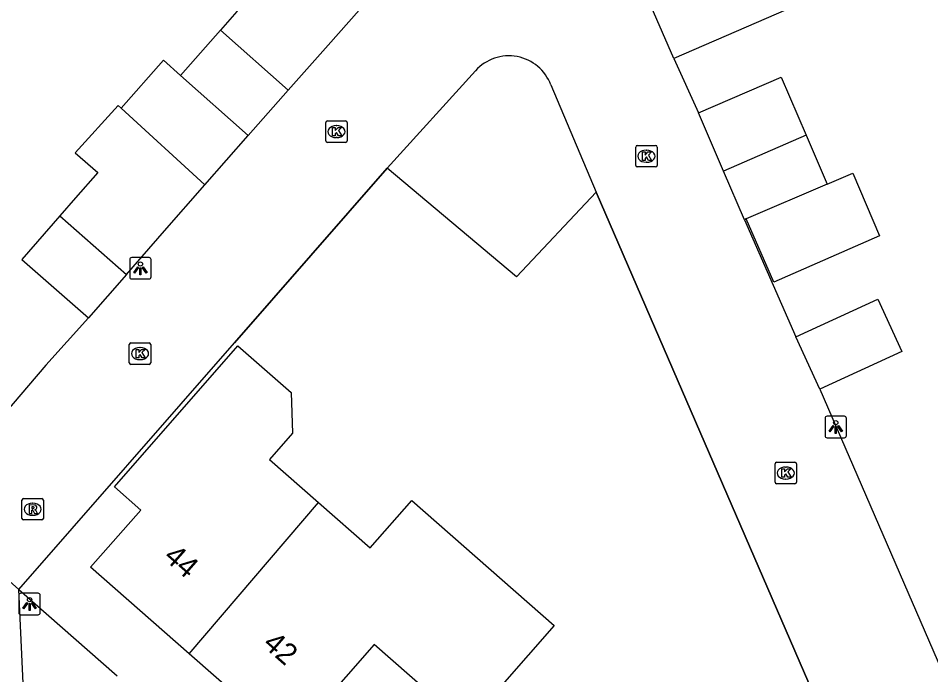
# Model space of a CAD drawing. Extents: x 158474 to 159560, y 388525 to 389605.
# Drawn here: x 158891.36 to 158933.91, y 388910.55 to 388941.14 of the extents above; entities that cross this region are included whole.
import ezdxf

# ---------------------------------------------------------------- set-up
doc = ezdxf.new("R2010")
doc.units = 0
for name, color, linetype in [('IMGEO_Kolk', 7, 'Continuous'), ('IMGEO_Lichtpunt', 7, 'Continuous'), ('IMGEO_Muur', 7, 'Continuous'), ('IMGEO_Pand', 7, 'Continuous'), ('IMGEO_Pand_nummerreeks', 7, 'Continuous'), ('IMGEO_Rijbaan_lokaal_open', 7, 'Continuous'), ('IMGEO_Rioolput', 7, 'Continuous'), ('IMGEO_Voetpad_open', 7, 'Continuous')]:
    doc.layers.add(name, color=color, linetype=linetype)

msp = doc.modelspace()

# ---------------------------------------------------------------- linework, layer by layer
at = {"layer": 'IMGEO_Kolk'}
for p, q in [((158905.696, 388935.435), (158905.696, 388936.287)), ((158905.771, 388936.361), (158906.623, 388936.361)), ((158906.184, 388936.141), (158906.209, 388936.141)), ((158906.697, 388936.287), (158906.697, 388935.435)), ((158906.207, 388935.581), (158906.182, 388935.581)), ((158906.623, 388935.361), (158905.771, 388935.361)), ((158920.223, 388935.216), (158921.075, 388935.216)), ((158920.148, 388934.29), (158920.148, 388935.142)), ((158920.636, 388934.996), (158920.661, 388934.996)), ((158921.149, 388935.142), (158921.149, 388934.29)), ((158920.659, 388934.436), (158920.634, 388934.436)), ((158921.075, 388934.216), (158920.223, 388934.216)), ((158896.535, 388925.089), (158896.535, 388925.941)), ((158896.61, 388926.015), (158897.462, 388926.015)), ((158897.023, 388925.795), (158897.048, 388925.795)), ((158897.536, 388925.941), (158897.536, 388925.089)), ((158897.462, 388925.015), (158896.61, 388925.015)), ((158897.046, 388925.235), (158897.021, 388925.235)), ((158926.646, 388919.524), (158926.646, 388920.376)), ((158926.721, 388920.45), (158927.573, 388920.45)), ((158927.647, 388920.376), (158927.647, 388919.524)), ((158927.134, 388920.23), (158927.159, 388920.23)), ((158927.573, 388919.45), (158926.721, 388919.45)), ((158927.157, 388919.67), (158927.132, 388919.67))]:
    msp.add_line(p, q, dxfattribs=at)
for points in [[(158905.696, 388935.435), (158905.696, 388936.287)], [(158905.771, 388936.361), (158906.623, 388936.361)], [(158906.017, 388936.061), (158906.14, 388936.061), (158906.14, 388935.91), (158906.27, 388936.061), (158906.434, 388936.061), (158906.288, 388935.91), (158906.441, 388935.661), (158906.289, 388935.661), (158906.204, 388935.825), (158906.14, 388935.758), (158906.14, 388935.661), (158906.017, 388935.661), (158906.017, 388936.061)], [(158906.697, 388936.287), (158906.697, 388935.435)], [(158906.623, 388935.361), (158905.771, 388935.361)], [(158920.223, 388935.216), (158921.075, 388935.216)], [(158920.148, 388934.29), (158920.148, 388935.142)], [(158920.469, 388934.916), (158920.592, 388934.916), (158920.592, 388934.765), (158920.722, 388934.916), (158920.886, 388934.916), (158920.74, 388934.765), (158920.893, 388934.516), (158920.741, 388934.516), (158920.656, 388934.68), (158920.592, 388934.613), (158920.592, 388934.516), (158920.469, 388934.516), (158920.469, 388934.916)], [(158921.149, 388935.142), (158921.149, 388934.29)], [(158921.075, 388934.216), (158920.223, 388934.216)], [(158896.535, 388925.089), (158896.535, 388925.941)], [(158896.61, 388926.015), (158897.462, 388926.015)], [(158897.536, 388925.941), (158897.536, 388925.089)], [(158896.856, 388925.715), (158896.979, 388925.715), (158896.979, 388925.564), (158897.109, 388925.715), (158897.273, 388925.715), (158897.127, 388925.564), (158897.28, 388925.315), (158897.128, 388925.315), (158897.043, 388925.479), (158896.979, 388925.412), (158896.979, 388925.315), (158896.856, 388925.315), (158896.856, 388925.715)], [(158897.462, 388925.015), (158896.61, 388925.015)], [(158926.646, 388919.524), (158926.646, 388920.376)], [(158926.721, 388920.45), (158927.573, 388920.45)], [(158927.647, 388920.376), (158927.647, 388919.524)], [(158926.967, 388920.15), (158927.09, 388920.15), (158927.09, 388919.999), (158927.22, 388920.15), (158927.384, 388920.15), (158927.238, 388919.999), (158927.391, 388919.75), (158927.239, 388919.75), (158927.154, 388919.914), (158927.09, 388919.847), (158927.09, 388919.75), (158926.967, 388919.75), (158926.967, 388920.15)], [(158927.573, 388919.45), (158926.721, 388919.45)]]:
    msp.add_lwpolyline(points, dxfattribs=at)
for centre, start, end in [((158905.773, 388936.285), 91.552, 178.448), ((158905.773, 388936.285), 91.552, 178.448), ((158906.621, 388936.285), 1.552, 88.448), ((158906.621, 388936.285), 1.552, 88.448), ((158905.773, 388935.437), 181.552, 268.448), ((158905.773, 388935.437), 181.552, 268.448), ((158906.621, 388935.437), 271.552, 358.448), ((158906.621, 388935.437), 271.552, 358.448), ((158920.225, 388935.14), 91.552, 178.448), ((158920.225, 388935.14), 91.552, 178.448), ((158921.073, 388935.14), 1.552, 88.448), ((158921.073, 388935.14), 1.552, 88.448), ((158920.225, 388934.292), 181.552, 268.448), ((158920.225, 388934.292), 181.552, 268.448), ((158921.073, 388934.292), 271.552, 358.448), ((158921.073, 388934.292), 271.552, 358.448), ((158896.612, 388925.939), 91.552, 178.448), ((158896.612, 388925.939), 91.552, 178.448), ((158897.46, 388925.939), 1.552, 88.448), ((158897.46, 388925.939), 1.552, 88.448), ((158896.612, 388925.091), 181.552, 268.448), ((158896.612, 388925.091), 181.552, 268.448), ((158897.46, 388925.091), 271.552, 358.448), ((158897.46, 388925.091), 271.552, 358.448), ((158926.723, 388920.374), 91.552, 178.448), ((158926.723, 388920.374), 91.552, 178.448), ((158927.571, 388920.374), 1.552, 88.448), ((158927.571, 388920.374), 1.552, 88.448), ((158926.723, 388919.526), 181.552, 268.448), ((158926.723, 388919.526), 181.552, 268.448), ((158927.571, 388919.526), 271.552, 358.448), ((158927.571, 388919.526), 271.552, 358.448)]:
    msp.add_arc(centre, 0.0765, start, end, dxfattribs=at)
for centre, major_axis, ratio, start_param, end_param in [((158906.183, 388935.861), (-0.387, 0.002), 0.722429, 4.712389, 7.853982), ((158906.208, 388935.861), (-0.39, 0.002), 0.717154, 1.570796, 4.712389), ((158920.635, 388934.716), (-0.387, 0.002), 0.722429, 4.712389, 7.853982), ((158920.66, 388934.716), (-0.39, 0.002), 0.717154, 1.570796, 4.712389), ((158897.022, 388925.515), (-0.387, 0.002), 0.722429, 4.712389, 7.853982), ((158897.047, 388925.515), (-0.39, 0.002), 0.717154, 1.570796, 4.712389), ((158927.133, 388919.95), (-0.387, 0.002), 0.722429, 4.712389, 7.853982), ((158927.158, 388919.95), (-0.39, 0.002), 0.717154, 1.570796, 4.712389)]:
    msp.add_ellipse(centre, major_axis=major_axis, ratio=ratio, start_param=start_param, end_param=end_param, dxfattribs=at)
at = {"layer": 'IMGEO_Lichtpunt'}
for p, q in [((158896.556, 388929.895), (158896.556, 388929.088)), ((158896.556, 388929.895), (158896.556, 388929.088)), ((158897.458, 388929.99), (158896.65, 388929.99)), ((158897.458, 388929.99), (158896.65, 388929.99)), ((158897.552, 388929.088), (158897.552, 388929.895)), ((158897.552, 388929.088), (158897.552, 388929.895)), ((158896.65, 388928.994), (158897.458, 388928.994)), ((158896.65, 388928.994), (158897.458, 388928.994)), ((158928.978, 388922.499), (158928.978, 388921.692)), ((158928.978, 388922.499), (158928.978, 388921.692)), ((158929.88, 388922.594), (158929.072, 388922.594)), ((158929.88, 388922.594), (158929.072, 388922.594)), ((158929.974, 388921.692), (158929.974, 388922.499)), ((158929.974, 388921.692), (158929.974, 388922.499)), ((158929.072, 388921.598), (158929.88, 388921.598)), ((158929.072, 388921.598), (158929.88, 388921.598)), ((158892.287, 388914.345), (158891.479, 388914.345)), ((158892.287, 388914.345), (158891.479, 388914.345)), ((158891.385, 388914.25), (158891.385, 388913.443)), ((158891.385, 388914.25), (158891.385, 388913.443)), ((158892.381, 388913.443), (158892.381, 388914.25)), ((158892.381, 388913.443), (158892.381, 388914.25)), ((158891.479, 388913.349), (158892.287, 388913.349)), ((158891.479, 388913.349), (158892.287, 388913.349))]:
    msp.add_line(p, q, dxfattribs=at)
for points in [[(158896.93, 388929.559), (158896.969, 388929.531), (158896.781, 388929.269), (158896.743, 388929.296), (158896.93, 388929.559)], [(158897.032, 388929.511), (158897.079, 388929.511), (158897.079, 388929.189), (158897.032, 388929.189), (158897.032, 388929.511)], [(158897.142, 388929.531), (158897.18, 388929.558), (158897.367, 388929.296), (158897.328, 388929.268), (158897.142, 388929.531)], [(158929.352, 388922.163), (158929.391, 388922.135), (158929.203, 388921.873), (158929.165, 388921.9), (158929.352, 388922.163)], [(158929.454, 388922.115), (158929.501, 388922.115), (158929.501, 388921.793), (158929.454, 388921.793), (158929.454, 388922.115)], [(158929.564, 388922.135), (158929.602, 388922.162), (158929.789, 388921.9), (158929.75, 388921.872), (158929.564, 388922.135)], [(158891.759, 388913.914), (158891.798, 388913.886), (158891.61, 388913.624), (158891.572, 388913.651), (158891.759, 388913.914)], [(158891.971, 388913.886), (158892.009, 388913.913), (158892.196, 388913.651), (158892.157, 388913.623), (158891.971, 388913.886)], [(158891.861, 388913.866), (158891.908, 388913.866), (158891.908, 388913.544), (158891.861, 388913.544), (158891.861, 388913.866)]]:
    msp.add_lwpolyline(points, dxfattribs=at)
for centre in [(158897.055, 388929.693), (158929.477, 388922.297), (158891.884, 388914.048)]:
    msp.add_circle(centre, 0.0994, dxfattribs=at)
for centre, start, end in [((158896.65, 388929.895), 90, 180), ((158896.65, 388929.895), 90, 180), ((158897.458, 388929.895), 0, 90), ((158897.458, 388929.895), 0, 90), ((158896.65, 388929.088), 180, 270), ((158896.65, 388929.088), 180, 270), ((158897.458, 388929.088), 270, 0), ((158897.458, 388929.088), 270, 360), ((158929.072, 388922.499), 90, 180), ((158929.072, 388922.499), 90, 180), ((158929.88, 388922.499), 0, 90), ((158929.88, 388922.499), 0, 90), ((158929.072, 388921.692), 180, 270), ((158929.072, 388921.692), 180, 270), ((158929.88, 388921.692), 270, 0), ((158929.88, 388921.692), 270, 360), ((158891.479, 388914.25), 90, 180), ((158891.479, 388914.25), 90, 180), ((158892.287, 388914.25), 0, 90), ((158892.287, 388914.25), 0, 90), ((158891.479, 388913.443), 180, 270), ((158891.479, 388913.443), 180, 270), ((158892.287, 388913.443), 270, 0), ((158892.287, 388913.443), 270, 360)]:
    msp.add_arc(centre, 0.0946, start, end, dxfattribs=at)
at = {"layer": 'IMGEO_Muur'}
for points in [[(158908.556, 388934.162), (158901.439, 388926.022)], [(158933.436, 388904.261), (158929.786, 388907.457), (158928.836, 388908.759), (158918.298, 388933.043)]]:
    msp.add_lwpolyline(points, dxfattribs=at)
at = {"layer": 'IMGEO_Pand'}
for points in [[(158923.539, 388946.194), (158926.865, 388947.644), (158929.146, 388942.413), (158921.925, 388939.265)], [(158903.874, 388945.502), (158901.941, 388943.315), (158902.649, 388942.689), (158901.555, 388941.452), (158900.788, 388940.584)], [(158921.925, 388939.265), (158920.6, 388942.321), (158919.655, 388944.501)], [(158907.741, 388942.085), (158905.808, 388939.898), (158903.947, 388937.792)], [(158900.788, 388940.584), (158898.926, 388938.478)], [(158903.947, 388937.792), (158900.788, 388940.584)], [(158898.926, 388938.478), (158898.127, 388939.184), (158896.155, 388936.952)], [(158908.556, 388934.162), (158912.68, 388938.701)], [(158902.086, 388935.686), (158898.926, 388938.478)], [(158923.07, 388936.743), (158926.931, 388938.404), (158928.095, 388935.697)], [(158903.947, 388937.792), (158902.086, 388935.686)], [(158916.192, 388938.038), (158918.298, 388933.043)], [(158896.155, 388936.952), (158896.02, 388937.075), (158894.012, 388934.878), (158895.064, 388933.959), (158894.029, 388932.773), (158893.293, 388931.931)], [(158896.155, 388936.952), (158900.063, 388933.382)], [(158924.242, 388934.018), (158923.07, 388936.743)], [(158900.063, 388933.382), (158902.086, 388935.686)], [(158928.095, 388935.697), (158924.242, 388934.018)], [(158928.095, 388935.697), (158929.076, 388933.418)], [(158918.298, 388933.043), (158914.585, 388929.097), (158908.556, 388934.162)], [(158925.215, 388931.757), (158924.242, 388934.018)], [(158929.076, 388933.418), (158930.27, 388933.932), (158931.52, 388931.003), (158926.591, 388928.853), (158925.293, 388931.79)], [(158896.408, 388929.21), (158898.179, 388931.238), (158900.063, 388933.382)], [(158929.076, 388933.418), (158925.293, 388931.79)], [(158893.293, 388931.931), (158891.521, 388929.902), (158894.636, 388927.182)], [(158893.293, 388931.931), (158896.408, 388929.21)], [(158925.293, 388931.79), (158925.215, 388931.757)], [(158896.408, 388929.21), (158894.636, 388927.182)], [(158927.61, 388926.294), (158931.442, 388928.052), (158932.561, 388925.613), (158928.728, 388923.855)], [(158928.728, 388923.855), (158927.61, 388926.294)], [(158899.326, 388911.528), (158894.73, 388915.557), (158897.071, 388918.227), (158895.838, 388919.309), (158901.6, 388925.881), (158904.082, 388923.706), (158904.151, 388921.813), (158903.069, 388920.578), (158905.354, 388918.575)], [(158899.326, 388911.528), (158905.354, 388918.575)], [(158905.354, 388918.575), (158907.764, 388916.461), (158909.704, 388918.674), (158916.349, 388912.847), (158912.713, 388908.701)], [(158912.265, 388908.19), (158907.959, 388911.966), (158903.989, 388907.439), (158899.326, 388911.528)]]:
    msp.add_lwpolyline(points, dxfattribs=at)
msp.add_arc((158914.233, 388937.296), 2.095, 20.7539, 137.865, dxfattribs=at)
at = {"layer": 'IMGEO_Rijbaan_lokaal_open'}
for points in [[(158921.925, 388939.265), (158923.07, 388936.743)], [(158891.387, 388914.523), (158901.439, 388926.022), (158908.556, 388934.162)], [(158918.298, 388933.043), (158928.836, 388908.759), (158929.786, 388907.457), (158933.436, 388904.261)], [(158925.215, 388931.757), (158927.61, 388926.294)], [(158894.636, 388927.182), (158892.645, 388924.975), (158890.671, 388922.663)], [(158928.728, 388923.855), (158935.982, 388907.162)], [(158886.632, 388918.744), (158891.387, 388914.523)], [(158891.767, 388906.111), (158891.387, 388914.523)]]:
    msp.add_lwpolyline(points, dxfattribs=at)
at = {"layer": 'IMGEO_Rioolput'}
for p, q in [((158891.529, 388917.836), (158891.529, 388918.688)), ((158891.604, 388918.762), (158892.456, 388918.762)), ((158892.53, 388918.688), (158892.53, 388917.836)), ((158892.017, 388918.542), (158892.042, 388918.542)), ((158892.456, 388917.762), (158891.604, 388917.762)), ((158892.04, 388917.982), (158892.015, 388917.982))]:
    msp.add_line(p, q, dxfattribs=at)
for points in [[(158891.529, 388917.836), (158891.529, 388918.688)], [(158891.604, 388918.762), (158892.456, 388918.762)], [(158892.53, 388918.688), (158892.53, 388917.836)], [(158892.118, 388918.46), (158891.866, 388918.462), (158891.866, 388918.062)], [(158891.866, 388918.062), (158891.99, 388918.062), (158891.99, 388918.224), (158892.001, 388918.224)], [(158892.044, 388918.381), (158891.99, 388918.381), (158891.99, 388918.3)], [(158891.99, 388918.3), (158892.042, 388918.3)], [(158892.048, 388918.195), (158892.119, 388918.062), (158892.259, 388918.062), (158892.194, 388918.188)], [(158892.456, 388917.762), (158891.604, 388917.762)]]:
    msp.add_lwpolyline(points, dxfattribs=at)
for centre, radius, start, end in [((158891.606, 388918.686), 0.0765, 91.552, 178.448), ((158891.606, 388918.686), 0.0765, 91.552, 178.448), ((158892.454, 388918.686), 0.0765, 1.552, 88.448), ((158892.454, 388918.686), 0.0765, 1.552, 88.448), ((158892, 388918.171), 0.0533, 26.0293, 88.6989), ((158892.026, 388918.489), 0.19, 274.7715, 282.9687), ((158892.05, 388918.285), 0.0964, 77.0061, 93.1865), ((158892.064, 388918.342), 0.0378, 276.6634, 79.6772), ((158892.117, 388918.35), 0.109, 350.3612, 89.416), ((158892.115, 388918.35), 0.112, 277.5842, 350.9817), ((158892.099, 388918.135), 0.108, 29.5134, 73.7905), ((158891.606, 388917.838), 0.0765, 181.552, 268.448), ((158891.606, 388917.838), 0.0765, 181.552, 268.448), ((158892.454, 388917.838), 0.0765, 271.552, 358.448), ((158892.454, 388917.838), 0.0765, 271.552, 358.448)]:
    msp.add_arc(centre, radius, start, end, dxfattribs=at)
for centre, major_axis, ratio, start_param, end_param in [((158892.016, 388918.262), (-0.387, 0.002), 0.722429, 4.712389, 7.853982), ((158892.041, 388918.262), (-0.39, 0.002), 0.717154, 1.570796, 4.712389)]:
    msp.add_ellipse(centre, major_axis=major_axis, ratio=ratio, start_param=start_param, end_param=end_param, dxfattribs=at)
at = {"layer": 'IMGEO_Voetpad_open'}
msp.add_lwpolyline([(158891.387, 388914.523), (158895.975, 388910.502)], dxfattribs=at)

# ---------------------------------------------------------------- texts
at = {"layer": 'IMGEO_Pand_nummerreeks'}
for s, p in [('44', (158898.086, 388915.967)), ('42', (158902.712, 388911.91))]:
    msp.add_text(s, height=1, rotation=318.7567, dxfattribs=at).set_placement(p)

doc.saveas('drawing.dxf')
